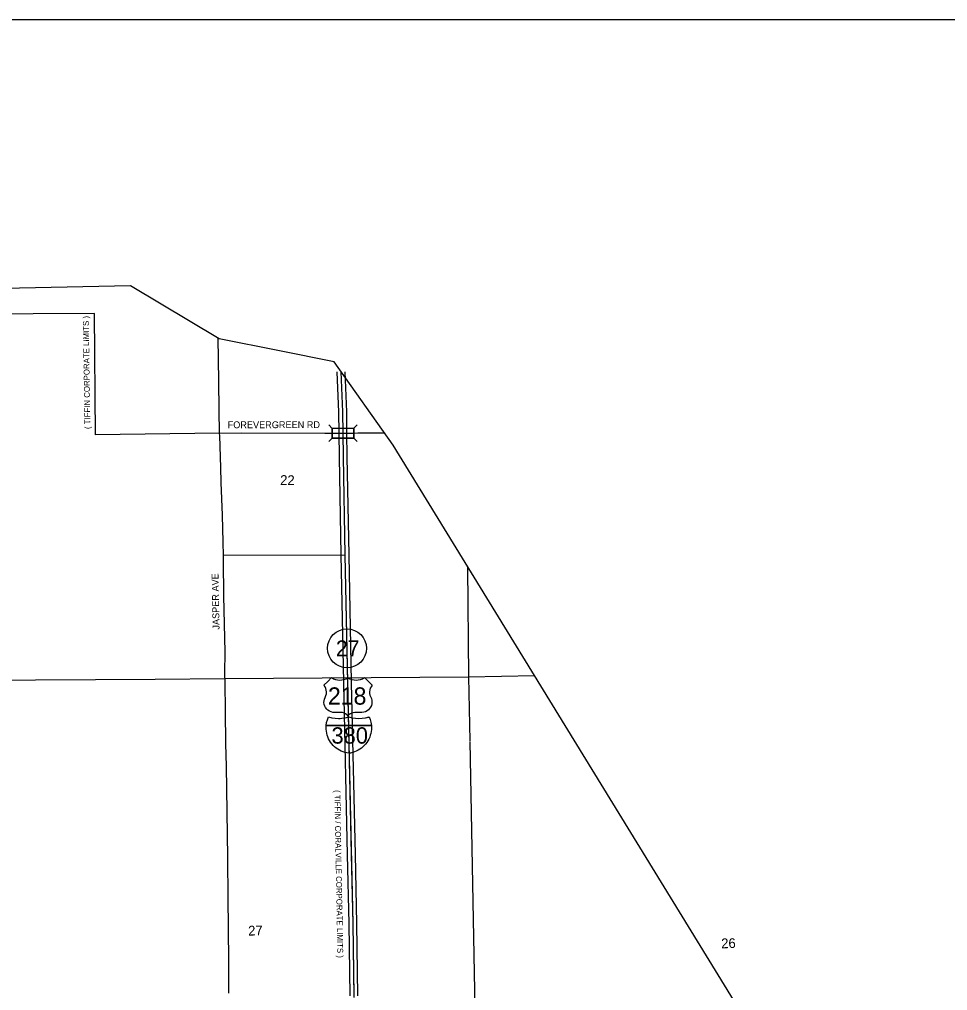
# Model space of a CAD drawing. Extents: x 281.94 to 289.14, y 116.09 to 120.89.
# Drawn here: x 284.748 to 286.65, y 118.797 to 120.787 of the extents above; entities that cross this region are included whole.
import ezdxf

# ---------------------------------------------------------------- set-up
doc = ezdxf.new("R2010")
doc.units = 0
for name, color, linetype in [('tdCiAdjCityStreetCL', 7, 'Continuous'), ('tdCiCityStreetCL', 7, 'Continuous'), ('tdCiCityStreetTxt', 7, 'Continuous'), ('tdCiCorpBndry', 7, 'Continuous'), ('tdCiCorpBndryPart', 7, 'Continuous'), ('tdCiCorpBndryTxt', 7, 'Continuous'), ('tdCiInt', 7, 'Continuous'), ('tdCiIntCL', 7, 'Continuous'), ('tdCiMapFrame', 7, 'Continuous'), ('tdCiMapPltShpe', 7, 'Continuous'), ('tdCiSecCL', 7, 'Continuous'), ('tdCiSecText', 7, 'Continuous'), ('tdCiSectLine', 7, 'Continuous'), ('tdCiSectNmbr', 7, 'Continuous'), ('tdCiShieldInt', 7, 'Continuous'), ('tdCiShieldPriStRte', 7, 'Continuous'), ('tdCiShieldPriUsRte', 7, 'Continuous'), ('tdCiStrucDataSec', 7, 'Continuous')]:
    doc.layers.add(name, color=color, linetype=linetype)

msp = doc.modelspace()

# ---------------------------------------------------------------- linework, layer by layer
at = {"layer": 'tdCiAdjCityStreetCL'}
msp.add_lwpolyline([(285.1657, 119.6884), (285.1652, 119.7155), (285.1639, 119.7713), (285.1612, 119.8382), (285.1602, 119.8688), (285.1583, 119.9334), (285.1581, 119.939), (285.202, 119.9396), (285.3736, 119.9391), (285.411, 119.9388), (285.4417, 119.9394), (285.4954, 119.9399)], dxfattribs=at)
at = {"layer": 'tdCiCityStreetCL'}
msp.add_lwpolyline([(285.177, 118.7913), (285.1766, 118.8574), (285.1758, 118.989), (285.1748, 119.0656), (285.1747, 119.0695), (285.1721, 119.2566), (285.171, 119.3024), (285.1699, 119.37), (285.1691, 119.4273), (285.1687, 119.4474), (285.1691, 119.491), (285.1665, 119.6051), (285.1659, 119.6778), (285.1657, 119.6884)], dxfattribs=at)
at = {"layer": 'tdCiCorpBndry'}
msp.add_lwpolyline([(285.4338, 118.7825), (285.4315, 118.9342), (285.4206, 119.4274), (285.4153, 119.6889), (285.1657, 119.6884), (285.1652, 119.7155), (285.1639, 119.7713), (285.1612, 119.8382), (285.1602, 119.8688), (285.1583, 119.9334), (285.1581, 119.939), (284.9038, 119.9359), (284.9013, 120.1845), (284.3984, 120.1814)], dxfattribs=at)
at = {"layer": 'tdCiCorpBndryPart'}
for points in [[(285.1583, 119.9334), (285.1581, 119.939), (284.9038, 119.9359), (284.9013, 120.1845), (284.3984, 120.1814), (284.4003, 119.9337), (284.1496, 119.9302), (283.9074, 119.9294), (283.901, 119.9293), (283.9085, 119.6773), (283.9409, 119.6776), (284.1542, 119.6796)], [(285.4338, 118.7825), (285.4315, 118.9342), (285.4206, 119.4274), (285.4153, 119.6889), (285.1657, 119.6884)]]:
    msp.add_lwpolyline(points, dxfattribs=at)
at = {"layer": 'tdCiInt'}
for points in [[(285.4257, 118.7859), (285.4235, 118.9341), (285.4204, 119.0752), (285.4126, 119.4272), (285.4126, 119.4287), (285.4073, 119.6887), (285.4073, 119.6897), (285.4037, 119.89), (285.4037, 119.8907), (285.403, 119.9387), (285.4027, 119.9821), (285.4027, 119.9822), (285.3993, 120.0644)], [(285.4417, 118.7861), (285.4395, 118.9344), (285.4364, 119.0756), (285.4286, 119.4276), (285.4286, 119.4291), (285.4233, 119.689), (285.4233, 119.69), (285.4197, 119.8903), (285.4197, 119.8909), (285.419, 119.9389), (285.4187, 119.9824), (285.4187, 119.9829), (285.4153, 120.065)]]:
    msp.add_lwpolyline(points, dxfattribs=at)
at = {"layer": 'tdCiIntCL'}
msp.add_lwpolyline([(285.4337, 118.786), (285.4315, 118.9342), (285.4284, 119.0754), (285.4206, 119.4274), (285.4206, 119.4289), (285.4153, 119.6889), (285.4153, 119.6898), (285.4117, 119.8902), (285.4117, 119.8908), (285.411, 119.9388), (285.4107, 119.9822), (285.4107, 119.9826), (285.4073, 120.0647)], dxfattribs=at)
at = {"layer": 'tdCiMapFrame'}
msp.add_lwpolyline([(289.038, 120.7868), (289.038, 116.1868), (282.038, 116.1868), (282.038, 120.7868), (289.038, 120.7868)], dxfattribs=at)
at = {"layer": 'tdCiMapPltShpe'}
for p, q in [((285.3929, 120.0852), (285.2807, 120.1078)), ((285.5135, 119.9142), (285.3929, 120.0852))]:
    msp.add_line(p, q, dxfattribs=at)
for points in [[(285.2807, 120.1078), (285.1574, 120.1326), (284.9751, 120.2412), (284.0977, 120.2226)], [(286.7119, 117.9469), (286.7118, 117.9629), (285.5135, 119.9142)]]:
    msp.add_lwpolyline(points, dxfattribs=at)
at = {"layer": 'tdCiSecCL'}
msp.add_lwpolyline([(285.1581, 119.939), (285.157, 119.9859), (285.1561, 120.0453), (285.1549, 120.1341)], dxfattribs=at)
at = {"layer": 'tdCiSectLine'}
for points in [[(285.6665, 119.6637), (285.6682, 119.4398), (285.6708, 119.3084)], [(285.0261, 119.4352), (285.1689, 119.4363), (285.6682, 119.4398), (285.8034, 119.4422)], [(284.1559, 119.43), (284.6579, 119.4326), (285.0261, 119.4352)], [(285.6708, 119.3069), (285.6871, 118.4319), (285.7018, 117.5775)]]:
    msp.add_lwpolyline(points, dxfattribs=at)
at = {"layer": 'tdCiShieldInt'}
msp.add_line((285.3766, 119.3401), (285.4692, 119.3401), dxfattribs=at)
for points in [[(285.405, 119.3546), (285.4084, 119.3548), (285.4152, 119.3557), (285.4229, 119.3575), (285.4296, 119.3559), (285.4364, 119.3549), (285.4432, 119.3545), (285.4501, 119.3548), (285.4569, 119.3557), (285.4645, 119.3575), (285.4667, 119.3521), (285.4682, 119.3465), (285.4692, 119.3401), (285.4694, 119.336), (285.4693, 119.332), (285.4688, 119.3279), (285.4681, 119.3239), (285.467, 119.3199), (285.4657, 119.3161), (285.464, 119.3123), (285.4621, 119.3087), (285.4599, 119.3053), (285.4574, 119.302), (285.4547, 119.299), (285.4518, 119.2961), (285.4486, 119.2935), (285.4453, 119.2912), (285.4418, 119.2891), (285.4381, 119.2873), (285.4343, 119.2858), (285.4303, 119.2845), (285.4264, 119.2836), (285.4229, 119.2831), (285.4188, 119.2837), (285.4149, 119.2847), (285.411, 119.2859), (285.4072, 119.2875), (285.4035, 119.2893), (285.4001, 119.2915), (285.3967, 119.2938), (285.3936, 119.2965), (285.3907, 119.2993), (285.388, 119.3024), (285.3856, 119.3057), (285.3834, 119.3092), (285.3815, 119.3128), (285.3799, 119.3166), (285.3786, 119.3204), (285.3776, 119.3244), (285.3769, 119.3284), (285.3765, 119.3325), (285.3764, 119.3366), (285.3766, 119.3401), (285.3774, 119.3459), (285.3789, 119.3514), (285.3812, 119.3575), (285.3879, 119.3559), (285.3947, 119.3549), (285.4016, 119.3545)], [(285.4229, 119.2831), (285.4188, 119.2837), (285.4149, 119.2847), (285.411, 119.2859), (285.4072, 119.2875), (285.4035, 119.2893), (285.4001, 119.2915), (285.3967, 119.2938), (285.3936, 119.2965), (285.3907, 119.2993), (285.388, 119.3024), (285.3856, 119.3057), (285.3834, 119.3092), (285.3815, 119.3128), (285.3799, 119.3166), (285.3786, 119.3204), (285.3776, 119.3244), (285.3769, 119.3284), (285.3765, 119.3325), (285.3764, 119.3366), (285.3766, 119.3401), (285.4692, 119.3401), (285.4694, 119.336), (285.4693, 119.332), (285.4688, 119.3279), (285.4681, 119.3239), (285.467, 119.3199), (285.4657, 119.3161), (285.464, 119.3123), (285.4621, 119.3087), (285.4599, 119.3053), (285.4574, 119.302), (285.4547, 119.299), (285.4518, 119.2961), (285.4486, 119.2935), (285.4453, 119.2912), (285.4418, 119.2891), (285.4381, 119.2873), (285.4343, 119.2858), (285.4304, 119.2845), (285.4264, 119.2836)], [(285.4692, 119.3401), (285.3766, 119.3401), (285.3774, 119.3459), (285.3789, 119.3514), (285.3812, 119.3575), (285.3879, 119.3559), (285.3947, 119.3549), (285.4016, 119.3545), (285.4084, 119.3548), (285.4152, 119.3557), (285.4229, 119.3575), (285.4296, 119.3559), (285.4364, 119.3549), (285.4432, 119.3545), (285.4501, 119.3548), (285.4569, 119.3557), (285.4636, 119.3572), (285.4645, 119.3575), (285.4667, 119.3521), (285.4682, 119.3465)]]:
    msp.add_lwpolyline(points, close=True, dxfattribs=at)
at = {"layer": 'tdCiShieldPriStRte'}
msp.add_circle((285.4192, 119.4981), 0.0398, dxfattribs=at)
at = {"layer": 'tdCiShieldPriUsRte'}
msp.add_lwpolyline([(285.3797, 119.4302), (285.3875, 119.438), (285.3914, 119.4359), (285.3956, 119.4344), (285.3999, 119.4335), (285.4046, 119.4331), (285.4087, 119.4335), (285.413, 119.4344), (285.4172, 119.4359), (285.4212, 119.438), (285.4251, 119.4359), (285.4293, 119.4344), (285.4336, 119.4335), (285.438, 119.4332), (285.4424, 119.4335), (285.4467, 119.4344), (285.4509, 119.4359), (285.4549, 119.438), (285.4705, 119.4225), (285.4684, 119.4195), (285.4668, 119.4163), (285.4658, 119.4128), (285.4653, 119.4092), (285.4655, 119.4056), (285.4663, 119.4021), (285.4679, 119.3983), (285.4693, 119.395), (285.4702, 119.3915), (285.4704, 119.3878), (285.4701, 119.3842), (285.4692, 119.3808), (285.4676, 119.3775), (285.4656, 119.3745), (285.4631, 119.3719), (285.4602, 119.3697), (285.457, 119.3681), (285.4535, 119.367), (285.4499, 119.3665), (285.4354, 119.3665), (285.4321, 119.3662), (285.4289, 119.3653), (285.4259, 119.3638), (285.4232, 119.3619), (285.4212, 119.3598), (285.4189, 119.3621), (285.4162, 119.3641), (285.4132, 119.3655), (285.41, 119.3663), (285.4072, 119.3665), (285.3936, 119.3665), (285.39, 119.3668), (285.3865, 119.3677), (285.3832, 119.3692), (285.3802, 119.3712), (285.3775, 119.3737), (285.3753, 119.3766), (285.3737, 119.3798), (285.3726, 119.3832), (285.372, 119.3868), (285.3721, 119.3904), (285.3728, 119.394), (285.3741, 119.3974), (285.376, 119.4016), (285.3769, 119.4051), (285.3771, 119.4087), (285.3768, 119.4123), (285.3758, 119.4158), (285.3743, 119.4191), (285.3723, 119.4221), (285.372, 119.4225)], close=True, dxfattribs=at)
at = {"layer": 'tdCiStrucDataSec'}
for points in [[(285.4329, 119.9489), (285.3889, 119.9487), (285.3818, 119.9558)], [(285.3889, 119.9487), (285.389, 119.9387), (285.389, 119.9287), (285.382, 119.9216)], [(285.389, 119.9387), (285.411, 119.9388), (285.433, 119.9389)], [(285.433, 119.9289), (285.433, 119.9389), (285.4329, 119.9489), (285.44, 119.956)], [(285.389, 119.9287), (285.433, 119.9289), (285.4401, 119.9219)]]:
    msp.add_lwpolyline(points, dxfattribs=at)
msp.add_lwpolyline([(285.3889, 119.9487), (285.4329, 119.9489), (285.433, 119.9289), (285.389, 119.9287)], close=True, dxfattribs=at)

# ---------------------------------------------------------------- texts
at = {"layer": 'tdCiCityStreetTxt'}
msp.add_text('JASPER AVE', height=0.014, rotation=91.1002, dxfattribs=at).set_placement((285.1579, 119.5366))
at = {"layer": 'tdCiCorpBndryTxt'}
for s, rotation, p in [('( TIFFIN CORPORATE LIMITS )', 90.8794, (284.8932, 119.9475)), ('( TIFFIN / CORALVILLE CORPORATE LIMITS )', 271.0446, (285.3933, 119.2077))]:
    msp.add_text(s, height=0.012, rotation=rotation, dxfattribs=at).set_placement(p)
at = {"layer": 'tdCiSecText'}
msp.add_text('FOREVERGREEN RD', height=0.014, rotation=0.0869, dxfattribs=at).set_placement((285.1745, 119.9491))
at = {"layer": 'tdCiSectNmbr'}
for s, rotation, p in [('22', 359.1993, (285.282, 119.833)), ('27', 1.3955, (285.2168, 118.9094)), ('26', 1.3962, (286.1865, 118.8834))]:
    msp.add_text(s, height=0.02, rotation=rotation, dxfattribs=at).set_placement(p)
at = {"layer": 'tdCiShieldInt'}
msp.add_text('380', height=0.03348, dxfattribs=at).set_placement((285.3874, 119.3028))
at = {"layer": 'tdCiShieldPriStRte'}
msp.add_text('27', height=0.03246, dxfattribs=at).set_placement((285.3965, 119.4819))
at = {"layer": 'tdCiShieldPriUsRte'}
msp.add_text('218', height=0.03541, dxfattribs=at).set_placement((285.38, 119.3827))

doc.saveas('drawing.dxf')
